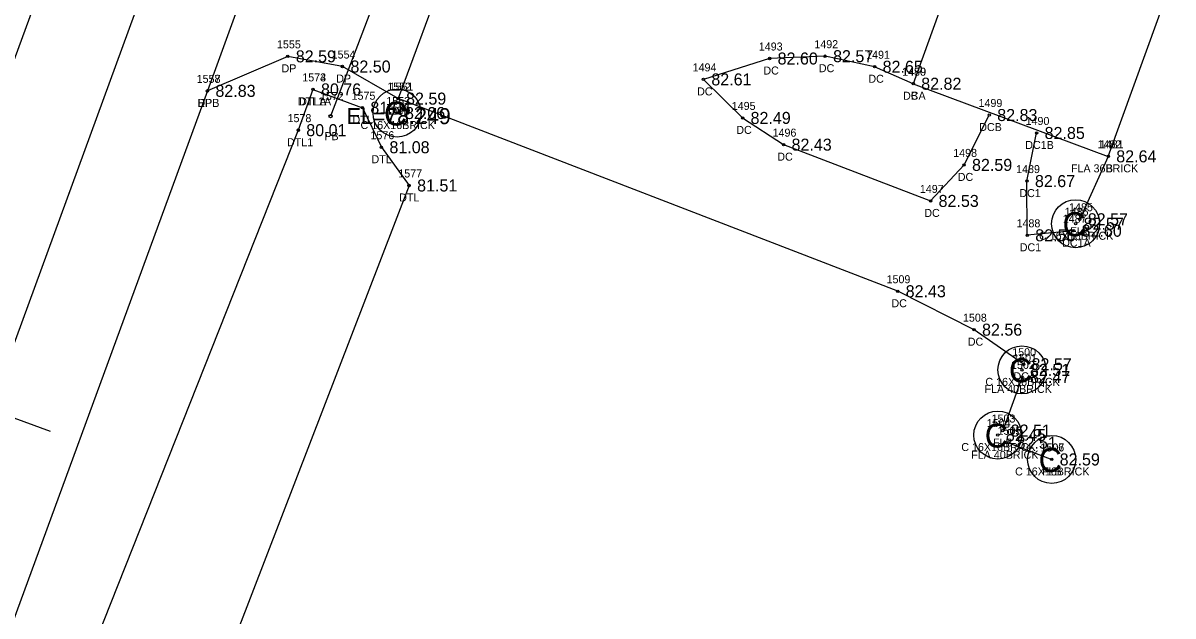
# Model space of a CAD drawing. Extents: x 2139392 to 2143384, y 505395 to 510520.
# Drawn here: x 2141170.6 to 2141314.3, y 509599 to 509673.1 of the extents above; entities that cross this region are included whole.
import ezdxf

# ---------------------------------------------------------------- set-up
doc = ezdxf.new("R2010")
doc.units = 0
for name, color, linetype in [('RD_EX_Bldg', 7, 'Continuous'), ('RD_EX_Bldg_txCode', 7, 'Continuous'), ('RD_EX_BldgApp', 7, 'Continuous'), ('RD_EX_BldgApp_txCode', 7, 'Continuous'), ('RD_EX_Conc', 7, 'Continuous'), ('RD_EX_Conc_txCode', 7, 'Continuous'), ('RD_EX_DR_Pipe', 7, 'Continuous'), ('RD_EX_DR_Pipe_txCode', 7, 'Continuous'), ('RD_EX_Driveway', 7, 'Continuous'), ('RD_EX_Driveway_txCode', 7, 'Continuous'), ('RD_EX_Fence_Other', 7, 'Continuous'), ('RD_EX_Fence_Other_txCode', 7, 'Continuous'), ('RD_EX_H2O', 7, 'Continuous'), ('RD_EX_H2O_txCode', 7, 'Continuous'), ('RD_EX_Road', 7, 'Continuous'), ('RD_EX_Road_txCode', 7, 'Continuous'), ('RD_EX_TX_Bldg_ELEV', 7, 'Continuous'), ('RD_EX_TX_BldgApp_ELEV', 7, 'Continuous'), ('RD_EX_TX_Conc_ELEV', 7, 'Continuous'), ('RD_EX_TX_Driveway_ELEV', 7, 'Continuous'), ('RD_EX_TX_Fence_Other_ELEV', 7, 'Continuous'), ('RD_EX_TX_H2O_ELEV', 7, 'Continuous'), ('RD_EX_TX_Road_ELEV', 7, 'Continuous'), ('RD_HC_Cl', 7, 'Continuous'), ('RD_HC_Data_Tic', 7, 'Continuous'), ('RD_SMD_Locator', 7, 'Continuous'), ('RD_TX_Pipe_ElevEX', 7, 'Continuous')]:
    doc.layers.add(name, color=color, linetype=linetype)

msp = doc.modelspace()

# ---------------------------------------------------------------- linework, layer by layer
at = {"layer": 'RD_EX_Bldg'}
msp.add_lwpolyline([(2141313.23, 509752.05), (2141304.22, 509727.14), (2141295.28, 509730.38), (2141286.85, 509707.27), (2141295.76, 509703.98), (2141281.84, 509665.49), (2141306.21, 509656.42), (2141337.67, 509743.19), (2141313.23, 509752.05)], dxfattribs=at)
at = {"layer": 'RD_EX_BldgApp'}
for centre in [(2141217.35, 509661.83), (2141302.13, 509648), (2141295.43, 509629.75), (2141292.41, 509621.61), (2141299.14, 509618.56)]:
    msp.add_circle(centre, 3, dxfattribs=at)
at = {"layer": 'RD_EX_Conc'}
for points in [[(2141281.84, 509665.49), (2141277.02, 509667.61), (2141270.83, 509668.93), (2141263.9, 509668.64), (2141255.62, 509666.03), (2141260.52, 509661.22), (2141265.64, 509657.88), (2141284.01, 509650.85), (2141288.19, 509655.35), (2141291.34, 509661.58)], [(2141295.63, 509630.45), (2141289.44, 509634.77), (2141279.9, 509639.57), (2141217.48, 509663.63)], [(2141301.88, 509647.13), (2141296.09, 509646.56), (2141296.05, 509653.33), (2141297.26, 509659.34)]]:
    msp.add_lwpolyline(points, dxfattribs=at)
at = {"layer": 'RD_EX_DR_Pipe'}
msp.add_line((2141218.07, 509685.09), (2141209.05, 509661.44), dxfattribs=at)
at = {"layer": 'RD_EX_Driveway'}
msp.add_lwpolyline([(2141204.36, 509694.36), (2141210.1, 509686.33), (2141216.21, 509682.06), (2141223.51, 509680.02), (2141217.48, 509663.63), (2141210.53, 509667.64), (2141203.7, 509668.91), (2141193.66, 509664.6)], dxfattribs=at)
at = {"layer": 'RD_EX_Fence_Other'}
for p, q in [((2141306.21, 509656.42), (2141302.65, 509648.56)), ((2141295.44, 509628.87), (2141293.02, 509622.17)), ((2141293.76, 509620.64), (2141299.14, 509618.56))]:
    msp.add_line(p, q, dxfattribs=at)
at = {"layer": 'RD_EX_H2O'}
for points in [[(2141206.85, 509664.78), (2141205.01, 509659.69), (2141170.77, 509573.35), (2141130.48, 509471.05), (2141121.47, 509445.58), (2141124.52, 509440.12), (2141132, 509437.49), (2141135.47, 509441.84)], [(2141206.85, 509664.78), (2141213.02, 509662.49), (2141215.4, 509657.56), (2141218.86, 509652.78), (2141186.74, 509569.46)]]:
    msp.add_lwpolyline(points, dxfattribs=at)
at = {"layer": 'RD_EX_Road'}
for points in [[(2141389.23, 510293.58), (2141374.66, 510243.58), (2141359.1, 510192.72), (2141341.17, 510140.58), (2141322.74, 510087.97), (2141303.61, 510035.12), (2141287.18, 509990.16), (2141276.99, 509962.02), (2141248.91, 509884.35), (2141213.37, 509787.47), (2141207.76, 509772.94), (2141199.35, 509749.36), (2141191.47, 509727.8), (2141175.93, 509686.04), (2141140.09, 509588.3), (2141106.08, 509494.11), (2141096.82, 509469.24), (2141063.82, 509378.98), (2141052.52, 509348.48), (2141043.48, 509323.88)], [(2141412.62, 510288.46), (2141398.29, 510238.16), (2141381.65, 510185.39), (2141379.05, 510176.51), (2141367.08, 510141.57), (2141363.58, 510131.95), (2141345.23, 510080.36), (2141326.05, 510027.03), (2141308.64, 509979.4), (2141271.24, 509876.37), (2141240, 509789.51), (2141233.78, 509773.43), (2141223.56, 509746.41), (2141212.18, 509714.93), (2141204.36, 509694.36), (2141197.99, 509676.56), (2141193.66, 509664.6), (2141161.61, 509577.24), (2141123.75, 509473.61), (2141115.5, 509450.65), (2141102.09, 509414.61), (2141086.27, 509371.27), (2141050.42, 509272.83)]]:
    msp.add_lwpolyline(points, dxfattribs=at)
at = {"layer": 'RD_HC_Cl'}
msp.add_line((2141333.53, 510081.69), (2140670.51, 508268.37), dxfattribs=at)
at = {"layer": 'RD_HC_Data_Tic'}
msp.add_line((2141166.49, 509624.86), (2141174.01, 509622.11), dxfattribs=at)
at = {"layer": 'RD_SMD_Locator'}
for centre, radius in [((2141203.7, 509668.91), 0.15), ((2141263.9, 509668.64), 0.15), ((2141270.83, 509668.93), 0.15), ((2141210.53, 509667.64), 0.15), ((2141277.02, 509667.61), 0.15), ((2141255.62, 509666.03), 0.15), ((2141281.84, 509665.49), 0.15), ((2141281.84, 509665.49), 0.15), ((2141193.66, 509664.6), 0.15), ((2141193.66, 509664.6), 0.15), ((2141206.85, 509664.78), 0.15), ((2141206.85, 509664.78), 0.15), ((2141213.02, 509662.49), 0.15), ((2141217.48, 509663.63), 0.15), ((2141217.48, 509663.63), 0.15), ((2141209.05, 509661.44), 0.2), ((2141217.35, 509661.83), 0.15), ((2141260.52, 509661.22), 0.15), ((2141291.34, 509661.58), 0.15), ((2141205.01, 509659.69), 0.15), ((2141297.26, 509659.34), 0.15), ((2141215.4, 509657.56), 0.15), ((2141265.64, 509657.88), 0.15), ((2141288.19, 509655.35), 0.15), ((2141306.21, 509656.42), 0.15), ((2141306.21, 509656.42), 0.15), ((2141218.86, 509652.78), 0.15), ((2141296.05, 509653.33), 0.15), ((2141284.01, 509650.85), 0.15), ((2141302.65, 509648.56), 0.15), ((2141301.88, 509647.13), 0.15), ((2141302.13, 509648), 0.15), ((2141296.09, 509646.56), 0.15), ((2141279.9, 509639.57), 0.15), ((2141289.44, 509634.77), 0.15), ((2141295.43, 509629.75), 0.15), ((2141295.63, 509630.45), 0.15), ((2141295.44, 509628.87), 0.15), ((2141292.41, 509621.61), 0.15), ((2141293.02, 509622.17), 0.15), ((2141293.76, 509620.64), 0.15), ((2141299.14, 509618.56), 0.15), ((2141299.14, 509618.56), 0.15)]:
    msp.add_circle(centre, radius, dxfattribs=at)

# ---------------------------------------------------------------- texts
at = {"layer": 'RD_EX_Bldg_txCode'}
for s, p in [('1479', (2141280.49, 509666.49)), ('B', (2141281.53, 509663.49)), ('1481', (2141305.15, 509657.42)), ('B', (2141305.91, 509654.42))]:
    msp.add_text(s, height=1, dxfattribs=at).set_placement(p)
at = {"layer": 'RD_EX_BldgApp'}
for p in [(2141215.72, 509660.27), (2141300.5, 509646.44), (2141293.8, 509628.19), (2141290.78, 509620.05), (2141297.51, 509616.99)]:
    msp.add_text('C', height=3, dxfattribs=at).set_placement(p)
at = {"layer": 'RD_EX_BldgApp_txCode'}
for s, p in [('1553', (2141216.01, 509662.83)), ('C 16X16BRICK', (2141212.79, 509659.83)), ('1486', (2141300.76, 509649)), ('C 16X16BRICK', (2141297.56, 509646)), ('1501', (2141294.33, 509630.75)), ('C 16X16BRICK', (2141290.86, 509627.75)), ('1504', (2141291.03, 509622.61)), ('C 16X16BRICK', (2141287.85, 509619.61)), ('1507', (2141297.75, 509619.56)), ('C 16X16BRICK', (2141294.57, 509616.56))]:
    msp.add_text(s, height=1, dxfattribs=at).set_placement(p)
at = {"layer": 'RD_EX_Conc_txCode'}
for s, p in [('1493', (2141262.55, 509669.64)), ('1492', (2141269.49, 509669.93)), ('1491', (2141275.96, 509668.61)), ('1494', (2141254.28, 509667.03)), ('DC', (2141263.12, 509666.64)), ('DC', (2141270.05, 509666.93)), ('1480', (2141280.45, 509666.49)), ('1551', (2141216.41, 509664.63)), ('DC', (2141276.24, 509665.61)), ('DC', (2141254.84, 509664.03)), ('DCA', (2141280.57, 509663.49)), ('DCB', (2141216.22, 509661.63)), ('1495', (2141259.17, 509662.22)), ('1499', (2141290, 509662.58)), ('1490', (2141295.88, 509660.34)), ('DC', (2141259.74, 509659.22)), ('1496', (2141264.27, 509658.88)), ('DCB', (2141290.09, 509659.58)), ('DC1B', (2141295.84, 509657.34)), ('DC', (2141264.86, 509655.88)), ('1498', (2141286.84, 509656.35)), ('DC', (2141287.41, 509653.35)), ('1489', (2141294.7, 509654.33)), ('1497', (2141282.67, 509651.85)), ('DC1', (2141295.1, 509651.33)), ('DC', (2141283.23, 509648.85)), ('1488', (2141294.75, 509647.56)), ('1487', (2141300.53, 509648.13)), ('DC1', (2141295.15, 509644.56)), ('DC1A', (2141300.45, 509645.13)), ('1509', (2141278.51, 509640.57)), ('DC', (2141279.12, 509637.57)), ('1508', (2141288.06, 509635.77)), ('DC', (2141288.66, 509632.77)), ('1500', (2141294.21, 509631.45)), ('DCA', (2141294.36, 509628.45))]:
    msp.add_text(s, height=1, dxfattribs=at).set_placement(p)
at = {"layer": 'RD_EX_DR_Pipe_txCode'}
for s, p in [('1572', (2141207.71, 509663.44)), ('PB', (2141208.27, 509658.44))]:
    msp.add_text(s, height=1, dxfattribs=at).set_placement(p)
at = {"layer": 'RD_EX_Driveway_txCode'}
for s, p in [('1555', (2141202.35, 509669.91)), ('1554', (2141209.18, 509668.64)), ('DP', (2141202.92, 509666.91)), ('1557', (2141192.32, 509665.6)), ('DP', (2141209.75, 509665.64)), ('1552', (2141216.13, 509664.63)), ('DPB', (2141192.41, 509662.6)), ('DP', (2141216.7, 509661.63))]:
    msp.add_text(s, height=1, dxfattribs=at).set_placement(p)
at = {"layer": 'RD_EX_Fence_Other_txCode'}
for s, p in [('1482', (2141304.87, 509657.42)), ('FLA 36BRICK', (2141301.55, 509654.42)), ('1485', (2141301.31, 509649.56)), ('FLB', (2141301.45, 509646.56)), ('1502', (2141294.06, 509629.87)), ('FLA 40BRICK', (2141290.76, 509626.87)), ('1503', (2141291.63, 509623.17)), ('1505', (2141292.38, 509621.64)), ('FLB', (2141291.81, 509620.17)), ('FLA 40BRICK', (2141289.09, 509618.64)), ('1506', (2141297.73, 509619.56)), ('FLB', (2141297.93, 509616.56))]:
    msp.add_text(s, height=1, dxfattribs=at).set_placement(p)
at = {"layer": 'RD_EX_H2O_txCode'}
for s, p in [('1573', (2141205.51, 509665.78)), ('1574', (2141205.51, 509665.78)), ('1575', (2141211.67, 509663.49)), ('DTL1A', (2141204.96, 509662.78)), ('DTLA', (2141205.12, 509662.78)), ('1578', (2141203.67, 509660.69)), ('DTL', (2141211.78, 509660.49)), ('DTL1', (2141203.6, 509657.69)), ('1576', (2141214.03, 509658.56)), ('DTL', (2141214.16, 509655.56)), ('1577', (2141217.51, 509653.78)), ('DTL', (2141217.62, 509650.78))]:
    msp.add_text(s, height=1, dxfattribs=at).set_placement(p)
at = {"layer": 'RD_EX_Road_txCode'}
for s, p in [('1558', (2141192.32, 509665.6)), ('EPL', (2141192.46, 509662.6))]:
    msp.add_text(s, height=1, dxfattribs=at).set_placement(p)
at = {"layer": 'RD_EX_TX_Bldg_ELEV'}
for s, p in [('82.82', (2141282.84, 509664.74)), ('82.64', (2141307.21, 509655.67))]:
    msp.add_text(s, height=1.5, dxfattribs=at).set_placement(p)
at = {"layer": 'RD_EX_TX_BldgApp_ELEV'}
for s, p in [('82.06', (2141218.35, 509661.08)), ('82.57', (2141303.13, 509647.25)), ('82.51', (2141296.43, 509629)), ('82.45', (2141293.42, 509620.86)), ('82.59', (2141300.14, 509617.81))]:
    msp.add_text(s, height=1.5, dxfattribs=at).set_placement(p)
at = {"layer": 'RD_EX_TX_Conc_ELEV'}
for s, p in [('82.60', (2141264.9, 509667.89)), ('82.57', (2141271.83, 509668.18)), ('82.65', (2141278.02, 509666.86)), ('82.61', (2141256.62, 509665.28)), ('82.82', (2141282.84, 509664.74)), ('82.59', (2141218.48, 509662.88)), ('82.49', (2141261.52, 509660.47)), ('82.83', (2141292.34, 509660.83)), ('82.85', (2141298.26, 509658.59)), ('82.43', (2141266.64, 509657.13)), ('82.59', (2141289.19, 509654.6)), ('82.67', (2141297.05, 509652.58)), ('82.53', (2141285.01, 509650.1)), ('82.56', (2141297.09, 509645.81)), ('82.60', (2141302.88, 509646.38)), ('82.43', (2141280.9, 509638.82)), ('82.56', (2141290.44, 509634.02)), ('82.57', (2141296.63, 509629.7))]:
    msp.add_text(s, height=1.5, dxfattribs=at).set_placement(p)
at = {"layer": 'RD_EX_TX_Driveway_ELEV'}
for s, p in [('82.59', (2141204.7, 509668.16)), ('82.50', (2141211.53, 509666.89)), ('82.83', (2141194.66, 509663.85)), ('82.59', (2141218.48, 509662.88))]:
    msp.add_text(s, height=1.5, dxfattribs=at).set_placement(p)
at = {"layer": 'RD_EX_TX_Fence_Other_ELEV'}
for s, p in [('82.64', (2141307.21, 509655.67)), ('82.57', (2141303.65, 509647.81)), ('82.47', (2141296.44, 509628.12)), ('82.51', (2141294.02, 509621.42)), ('82.51', (2141294.76, 509619.89)), ('82.59', (2141300.14, 509617.81))]:
    msp.add_text(s, height=1.5, dxfattribs=at).set_placement(p)
at = {"layer": 'RD_EX_TX_H2O_ELEV'}
for s, p in [('80.76', (2141207.85, 509664.03)), ('80.76', (2141207.85, 509664.03)), ('81.04', (2141214.02, 509661.74)), ('80.01', (2141206.01, 509658.94)), ('81.08', (2141216.4, 509656.81)), ('81.51', (2141219.86, 509652.03))]:
    msp.add_text(s, height=1.5, dxfattribs=at).set_placement(p)
at = {"layer": 'RD_EX_TX_Road_ELEV'}
msp.add_text('82.83', height=1.5, dxfattribs=at).set_placement((2141194.66, 509663.85))
at = {"layer": 'RD_TX_Pipe_ElevEX'}
msp.add_text('EL=78.249', height=2, dxfattribs=at).set_placement((2141211.05, 509660.44))

doc.saveas('drawing.dxf')
